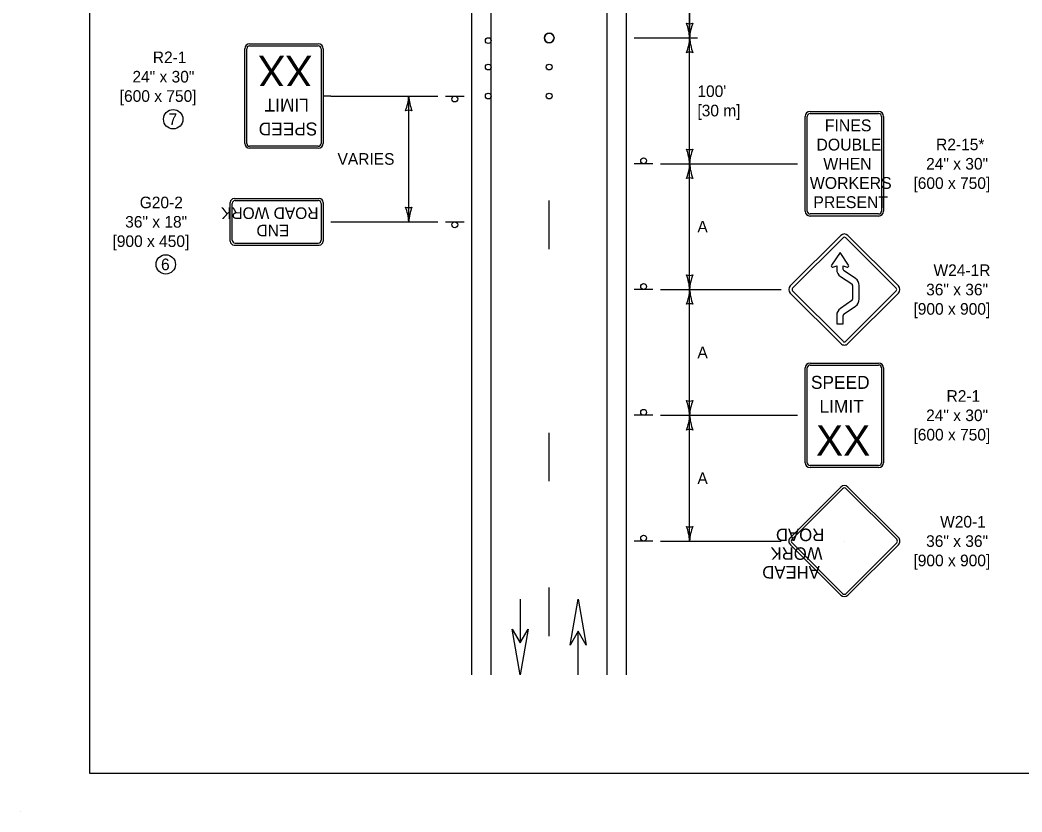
# Model space of a CAD drawing. Extents: x 49991.4 to 50021, y 49987.6 to 50011.4.
# Drawn here: x 49999.98 to 50005.15, y 49999.86 to 50003.95 of the extents above; entities that cross this region are included whole.
import ezdxf

# ---------------------------------------------------------------- set-up
doc = ezdxf.new("R2010")
doc.units = 0
for name, color, linetype in [('Level 1', 7, 'Continuous'), ('Level 2', 7, 'Continuous'), ('Level 3', 7, 'Continuous')]:
    doc.layers.add(name, color=color, linetype=linetype)

# ---------------------------------------------------------------- blocks, each defined once
blk = doc.blocks.new('W24-1 R')
at = {"layer": 'Level 1'}
for p, q in [((0.1984, 0.143), (0.1652, 0.0946)), ((0.2317, 0.0946), (0.1984, 0.143)), ((0.1708, 0.0869), (0.1858, 0.0916)), ((0.1858, 0.0916), (0.1858, 0.078)), ((0.2111, 0.078), (0.2111, 0.0916)), ((0.2111, 0.0916), (0.226, 0.0869)), ((0.2002, 0.051), (0.2442, 0.0216)), ((0.2582, 0.0426), (0.2143, 0.0721)), ((0.2473, 0.0156), (0.2473, -0.0371)), ((0.2726, -0.0371), (0.2726, 0.0156)), ((0.2442, -0.043), (0.2, -0.0731)), ((0.2142, -0.094), (0.2584, -0.064)), ((0.1858, -0.0996), (0.1858, -0.1324)), ((0.2111, -0.1324), (0.2111, -0.1003)), ((0.1858, -0.1324), (0.2111, -0.1324))]:
    blk.add_line(p, q, dxfattribs=at)
for points in [[(0.0058, 0.014), (0.2013, 0.2095)], [(0.0146, 0.0052), (0.2101, 0.2007)], [(0.2205, 0.2007), (0.416, 0.0052)], [(0.2293, 0.2095), (0.4248, 0.014)], [(0.2013, -0.2095), (0.0058, -0.014)], [(0.2101, -0.2007), (0.0146, -0.0052)], [(0.416, -0.0052), (0.2205, -0.2007)], [(0.4248, -0.014), (0.2293, -0.2095)]]:
    blk.add_lwpolyline(points, dxfattribs=at)
for centre, radius, start, end in [((0.2153, 0.1955), 0.0198, 45, 135), ((0.2153, 0.1955), 0.00735, 45, 135), ((0.1693, 0.0917), 0.00506, 145.4837, 287.3618), ((0.2182, 0.078), 0.0325, 180, 236.1761), ((0.2182, 0.078), 0.00717, 180, 236.1761), ((0.2275, 0.0917), 0.00506, 252.6382, 34.5163), ((0.2402, 0.0156), 0.0325, 0, 56.1761), ((0.0198, 0), 0.0198, 135, 225), ((0.0198, 0), 0.00735, 135, 225), ((0.2402, 0.0156), 0.00717, 0, 56.1761), ((0.4108, 0), 0.00735, 315, 45), ((0.4108, 0), 0.0198, 315, 45), ((0.2402, -0.0371), 0.00717, 304.2095, 0.0514), ((0.2402, -0.0371), 0.0325, 304.2095, 0.0482), ((0.2182, -0.0999), 0.0325, 124.2095, 180), ((0.2182, -0.0999), 0.00717, 124.2095, 182.7638), ((0.2153, -0.1955), 0.0198, 225, 315), ((0.2153, -0.1955), 0.00735, 225, 315)]:
    blk.add_arc(centre, radius, start, end, dxfattribs=at)

msp = doc.modelspace()

# ---------------------------------------------------------------- linework, layer by layer
at = {"layer": 'Level 1'}
for p, q in [((50002.3115, 50000.5714), (50002.3115, 50010.7538)), ((50002.4115, 50000.5714), (50002.4115, 50010.7538)), ((50003.0115, 50000.5714), (50003.0115, 50010.7538)), ((50003.1115, 50000.5714), (50003.1115, 50010.7538)), ((50003.4375, 50004.5714), (50003.4375, 50003.8622)), ((50001.1381, 50003.3175), (50001.1381, 50003.807)), ((50001.1486, 50003.3175), (50001.1486, 50003.807)), ((50001.1634, 50003.8323), (50001.5178, 50003.8323)), ((50001.1634, 50003.8217), (50001.5178, 50003.8217)), ((50001.5326, 50003.807), (50001.5326, 50003.3175)), ((50001.5431, 50003.807), (50001.5431, 50003.3175)), ((50002.1755, 50003.5622), (50002.2715, 50003.5622)), ((50004.0346, 50002.9675), (50004.0346, 50003.4569)), ((50004.0451, 50002.9675), (50004.0451, 50003.4569)), ((50004.0599, 50003.4822), (50004.4143, 50003.4822)), ((50004.0599, 50003.4717), (50004.4143, 50003.4717)), ((50004.2371, 50003.4822), (50004.2371, 50003.4822)), ((50004.4291, 50003.4569), (50004.4291, 50002.9675)), ((50004.4396, 50003.4569), (50004.4396, 50002.9675)), ((50001.5178, 50003.3027), (50001.1634, 50003.3027)), ((50001.5178, 50003.2922), (50001.1634, 50003.2922)), ((50001.3406, 50003.2922), (50001.3406, 50003.2922)), ((50003.2475, 50003.2122), (50003.1515, 50003.2122)), ((50001.0832, 50003.0323), (50001.5232, 50003.0323)), ((50001.0881, 50003.0222), (50001.5181, 50003.0222)), ((50002.7115, 50002.7716), (50002.7115, 50003.0216)), ((50001.0631, 50002.8122), (50001.0631, 50003.0122)), ((50001.0731, 50002.8172), (50001.0731, 50003.0072)), ((50001.5331, 50003.0072), (50001.5331, 50002.8172)), ((50001.5431, 50003.0122), (50001.5431, 50002.8122)), ((50004.4143, 50002.9527), (50004.0599, 50002.9527)), ((50004.4143, 50002.9421), (50004.0599, 50002.9421)), ((50002.1755, 50002.9122), (50002.2715, 50002.9122)), ((50001.0831, 50002.7922), (50001.5231, 50002.7922)), ((50001.0881, 50002.8022), (50001.5181, 50002.8022)), ((50003.2475, 50002.5622), (50003.1515, 50002.5622)), ((50004.0346, 50001.6675), (50004.0346, 50002.1569)), ((50004.0451, 50001.6675), (50004.0451, 50002.1569)), ((50004.0599, 50002.1823), (50004.4143, 50002.1823)), ((50004.0599, 50002.1717), (50004.4143, 50002.1717)), ((50004.2371, 50002.1823), (50004.2371, 50002.1823)), ((50004.4291, 50002.1569), (50004.4291, 50001.6675)), ((50004.4396, 50002.1569), (50004.4396, 50001.6675)), ((50003.2475, 50001.9122), (50003.1515, 50001.9122)), ((50002.7115, 50001.5716), (50002.7115, 50001.8216)), ((50004.4143, 50001.6527), (50004.0599, 50001.6527)), ((50004.4143, 50001.6422), (50004.0599, 50001.6422)), ((50004.2185, 50001.5416), (50003.9578, 50001.2808)), ((50004.2273, 50001.5328), (50003.9666, 50001.272)), ((50004.2185, 50001.5416), (50004.2185, 50001.5416)), ((50004.2273, 50001.5328), (50004.2273, 50001.5328)), ((50004.5077, 50001.272), (50004.2469, 50001.5328)), ((50004.5165, 50001.2808), (50004.2557, 50001.5416)), ((50003.2475, 50001.2622), (50003.1515, 50001.2622)), ((50004.2371, 50001.2622), (50004.2371, 50001.2622)), ((50004.2371, 50001.2622), (50004.2371, 50001.2622)), ((50004.2371, 50001.2622), (50004.2371, 50001.2622)), ((50003.9578, 50001.2436), (50004.2185, 50000.9829)), ((50003.9666, 50001.2524), (50004.2273, 50000.9917)), ((50004.2469, 50000.9917), (50004.5077, 50001.2524)), ((50004.2557, 50000.9829), (50004.5165, 50001.2436)), ((50002.7115, 50000.7716), (50002.7115, 50001.0216)), ((50002.5612, 50000.9615), (50002.5612, 50000.7356)), ((50002.5615, 50000.9615), (50002.5615, 50000.7356)), ((50002.8609, 50000.5714), (50002.8609, 50000.7973)), ((50002.8612, 50000.5714), (50002.8612, 50000.7973)), ((49999.9766, 49999.8624), (49999.9766, 49999.8624))]:
    msp.add_line(p, q, dxfattribs=at)
for points in [[(50008.6146, 50011.2628), (50000.3356, 50011.2628), (50000.3356, 50000.0624), (50008.6146, 50000.0624)], [(50002.8192, 50000.725), (50002.8609, 50000.9615), (50002.9028, 50000.725), (50002.8609, 50000.7972)], [(50002.6032, 50000.8079), (50002.5615, 50000.5714), (50002.5196, 50000.8079), (50002.5615, 50000.7357)]]:
    msp.add_lwpolyline(points, close=True, dxfattribs=at)
for centre, radius in [((50002.3966, 50003.8486), 0.015), ((50002.7114, 50003.8622), 0.025), ((50002.3966, 50003.7122), 0.015), ((50002.7115, 50003.7122), 0.015), ((50002.2235, 50003.547), 0.0152), ((50002.3966, 50003.5622), 0.015), ((50002.7115, 50003.5622), 0.015), ((50002.7115, 50003.5622), 0.015), ((50003.1995, 50003.2275), 0.0152), ((50002.2235, 50002.897), 0.0152), ((50003.1995, 50002.5775), 0.0152), ((50003.1995, 50001.9275), 0.0152), ((50003.1995, 50001.2775), 0.0152)]:
    msp.add_circle(centre, radius, dxfattribs=at)
for centre, radius, start, end in [((50002.7114, 50003.8622), 0.025, 21.4014, 201.4014), ((50002.7114, 50003.8622), 0.025, 201.4014, 21.4014), ((50001.1634, 50003.807), 0.0253, 90, 180), ((50001.1634, 50003.807), 0.0148, 90, 180), ((50001.5178, 50003.807), 0.0253, 360, 90), ((50001.5178, 50003.807), 0.0148, 360, 90), ((50004.0599, 50003.4569), 0.0253, 90, 180), ((50004.0599, 50003.4569), 0.0148, 90, 180), ((50004.4143, 50003.4569), 0.0253, 0, 90), ((50004.4143, 50003.4569), 0.0148, 0, 90), ((50001.1634, 50003.3175), 0.0253, 180, 270), ((50001.1634, 50003.3175), 0.0148, 180, 270), ((50001.5178, 50003.3175), 0.0148, 270, 360), ((50001.5178, 50003.3175), 0.0253, 270, 360), ((50001.0832, 50003.0122), 0.02, 90, 180), ((50001.0881, 50003.0072), 0.015, 90, 180), ((50001.5181, 50003.0072), 0.015, 360, 90), ((50001.5232, 50003.0122), 0.02, 360, 90), ((50004.0599, 50002.9675), 0.0253, 180, 270), ((50004.0599, 50002.9675), 0.0148, 180, 270), ((50004.4143, 50002.9675), 0.0148, 270, 360), ((50004.4143, 50002.9675), 0.0253, 270, 360), ((50001.0831, 50002.8122), 0.02, 180, 270), ((50001.0881, 50002.8172), 0.015, 180, 270), ((50001.5181, 50002.8172), 0.015, 270, 360), ((50001.5231, 50002.8122), 0.02, 270, 360), ((50004.0599, 50002.1569), 0.0253, 90, 180), ((50004.0599, 50002.1569), 0.0148, 90, 180), ((50004.4143, 50002.1569), 0.0253, 0, 90), ((50004.4143, 50002.1569), 0.0148, 0, 90), ((50004.0599, 50001.6675), 0.0253, 180, 270), ((50004.0599, 50001.6675), 0.0148, 180, 270), ((50004.4143, 50001.6675), 0.0148, 270, 360), ((50004.4143, 50001.6675), 0.0253, 270, 360), ((50004.2371, 50001.523), 0.0263, 45.0001, 134.9999), ((50004.2371, 50001.523), 0.0139, 45.0001, 134.9999), ((50003.9764, 50001.2622), 0.0263, 134.9999, 225.0001), ((50003.9764, 50001.2622), 0.0139, 134.9999, 225.0001), ((50004.4978, 50001.2622), 0.0139, 314.9999, 45.0001), ((50004.4978, 50001.2622), 0.0263, 314.9999, 45.0001), ((50004.2371, 50001.0015), 0.0263, 225.0001, 314.9999), ((50004.2371, 50001.0015), 0.0139, 225.0001, 314.9999)]:
    msp.add_arc(centre, radius, start, end, dxfattribs=at)
at = {"layer": 'Level 2'}
for centre in [(50000.7681, 50003.4422), (50000.7298, 50002.6922)]:
    msp.add_circle(centre, 0.0501, dxfattribs=at)
at = {"layer": 'Level 3'}
for p, q in [((50003.4375, 50003.8622), (50003.4375, 50004.5714)), ((50003.1515, 50003.8622), (50003.4775, 50003.8622)), ((50003.4375, 50003.2122), (50003.4375, 50003.8622)), ((50001.5831, 50003.5622), (50001.5431, 50003.5622)), ((50001.5831, 50003.5622), (50002.1355, 50003.5622)), ((50001.9855, 50002.9122), (50001.9855, 50003.5622)), ((50003.2875, 50003.2122), (50003.9946, 50003.2122)), ((50003.4375, 50002.5622), (50003.4375, 50003.2122)), ((50001.5831, 50002.9122), (50002.1355, 50002.9122)), ((50003.2875, 50002.5622), (50003.91, 50002.5622)), ((50003.4375, 50001.9122), (50003.4375, 50002.5622)), ((50003.2875, 50001.9122), (50003.9946, 50001.9122)), ((50003.4375, 50001.2622), (50003.4375, 50001.9122)), ((50003.2875, 50001.2622), (50003.91, 50001.2622))]:
    msp.add_line(p, q, dxfattribs=at)
for centre, radius, start, end in [((50003.4375, 50003.9904), 0.0548, 252.1388, 287.8612), ((50003.2048, 50003.8507), 0.233, 2.8273, 22.0772), ((50003.6596, 50003.8531), 0.2223, 157.456, 177.6395), ((50003.2154, 50003.8714), 0.2223, 337.456, 357.6395), ((50003.6702, 50003.8737), 0.233, 182.8273, 202.0772), ((50003.4375, 50003.734), 0.0548, 72.1388, 107.8612), ((50001.7634, 50003.5714), 0.2223, 337.456, 357.6395), ((50002.2182, 50003.5737), 0.233, 182.8273, 202.0772), ((50001.9855, 50003.434), 0.0548, 72.1388, 107.8612), ((50003.4375, 50003.3404), 0.0548, 252.1388, 287.8612), ((50003.2048, 50003.2007), 0.233, 2.8273, 22.0772), ((50003.6596, 50003.2031), 0.2223, 157.456, 177.6395), ((50003.2154, 50003.2214), 0.2223, 337.456, 357.6395), ((50003.6702, 50003.2237), 0.233, 182.8273, 202.0772), ((50003.4375, 50003.084), 0.0548, 72.1388, 107.8612), ((50001.9855, 50003.0404), 0.0548, 252.1388, 287.8612), ((50001.7528, 50002.9007), 0.233, 2.8273, 22.0772), ((50002.2076, 50002.9031), 0.2223, 157.456, 177.6395), ((50003.4375, 50002.6904), 0.0548, 252.1388, 287.8612), ((50003.2048, 50002.5507), 0.233, 2.8273, 22.0772), ((50003.6596, 50002.5531), 0.2223, 157.456, 177.6395), ((50003.2154, 50002.5714), 0.2223, 337.456, 357.6395), ((50003.6702, 50002.5737), 0.233, 182.8273, 202.0772), ((50003.4375, 50002.434), 0.0548, 72.1388, 107.8612), ((50003.4375, 50002.0404), 0.0548, 252.1388, 287.8612), ((50003.2048, 50001.9007), 0.233, 2.8273, 22.0772), ((50003.6596, 50001.9031), 0.2223, 157.456, 177.6395), ((50003.2154, 50001.9214), 0.2223, 337.456, 357.6395), ((50003.6702, 50001.9237), 0.233, 182.8273, 202.0772), ((50003.4375, 50001.784), 0.0548, 72.1388, 107.8612), ((50003.4375, 50001.3904), 0.0548, 252.1388, 287.8612), ((50003.2048, 50001.2507), 0.233, 2.8273, 22.0772), ((50003.6596, 50001.2531), 0.2223, 157.456, 177.6395)]:
    msp.add_arc(centre, radius, start, end, dxfattribs=at)

# ---------------------------------------------------------------- block references
at = {"layer": 'Level 1', "xscale": 1.3333547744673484, "yscale": 1.3333547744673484}
msp.add_blockref('W24-1 R', (50003.95, 50002.5622), dxfattribs=at)

# ---------------------------------------------------------------- texts
at = {"layer": 'Level 1'}
for s, height, p in [('XX', 0.15772, (50001.4877, 50003.7712)), ('LIMIT', 0.06695, (50001.4694, 50003.5492)), ('SPEED', 0.06695, (50001.5137, 50003.4254)), ('ROAD WORK', 0.06, (50001.519, 50002.9869)), ('END', 0.06, (50001.3683, 50002.8969)), ('ROAD', 0.06453, (50004.133, 50001.3267)), ('WORK', 0.06453, (50004.1239, 50001.23)), ('AHEAD', 0.06453, (50004.1102, 50001.1332))]:
    msp.add_text(s, height=height, rotation=180, dxfattribs=at).set_placement(p)
for s, height, p in [('FINES', 0.06118, (50004.136, 50003.3799)), ('DOUBLE', 0.06118, (50004.0925, 50003.2807)), ('WHEN', 0.06118, (50004.128, 50003.1816)), ('WORKERS', 0.06118, (50004.0586, 50003.0824)), ('PRESENT', 0.06118, (50004.0766, 50002.9833)), ('SPEED', 0.06695, (50004.064, 50002.049)), ('LIMIT', 0.06695, (50004.1083, 50001.9252)), ('XX', 0.15772, (50004.09, 50001.7033))]:
    msp.add_text(s, height=height, dxfattribs=at).set_placement(p)
at = {"layer": 'Level 2'}
for s, p in [('R2-1', (50000.6629, 50003.7322)), ('24" x 30"', (50000.5574, 50003.6322)), ('[600 x 750]', (50000.4918, 50003.5322)), ("100'", (50003.4775, 50003.5572)), ('[30 m]', (50003.4775, 50003.4572)), ('7', (50000.7443, 50003.4122)), ('R2-15*', (50004.7112, 50003.2822)), ('VARIES', (50001.6175, 50003.2072)), ('24" x 30"', (50004.6596, 50003.1822)), ('[600 x 750]', (50004.5941, 50003.0822)), ('G20-2', (50000.5952, 50002.9822)), ('36" x 18"', (50000.52, 50002.8822)), ('A', (50003.4775, 50002.8572)), ('[900 x 450]', (50000.4544, 50002.7822)), ('6', (50000.7052, 50002.6622)), ('W24-1R', (50004.6978, 50002.6322)), ('36" x 36"', (50004.6596, 50002.5322)), ('[900 x 900]', (50004.5941, 50002.4322)), ('A', (50003.4775, 50002.2072)), ('R2-1', (50004.7652, 50001.9822)), ('24" x 30"', (50004.6596, 50001.8822)), ('[600 x 750]', (50004.5941, 50001.7822)), ('A', (50003.4775, 50001.5572)), ('W20-1', (50004.7319, 50001.3322)), ('36" x 36"', (50004.6596, 50001.2322)), ('[900 x 900]', (50004.5941, 50001.1322))]:
    msp.add_text(s, height=0.06, dxfattribs=at).set_placement(p)

doc.saveas('drawing.dxf')
